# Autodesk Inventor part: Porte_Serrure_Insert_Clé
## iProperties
Created: 2009-01
Part Number: Porte_Serrure_Insert_Clé
Document SubType Name: Modeling
Designer: claivier
Author: claivier
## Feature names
1. Base1
